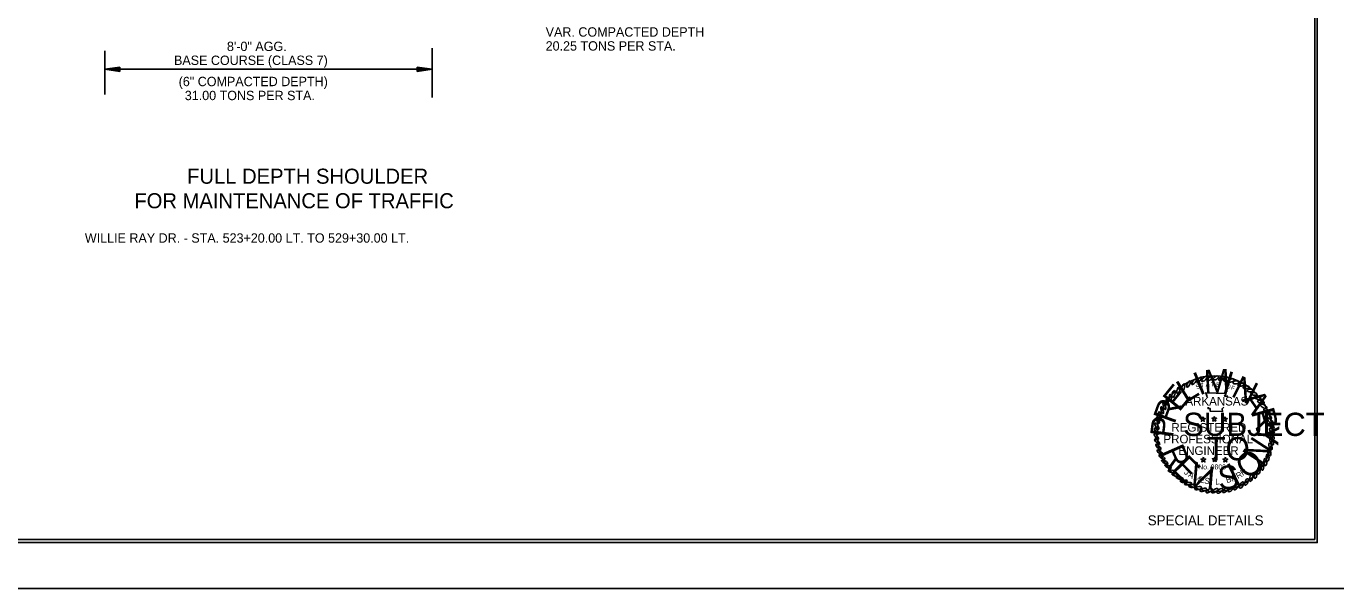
# Model space of a CAD drawing. Extents: x 714919 to 718439, y 1619644 to 1621844.
# Drawn here: x 716329 to 718439, y 1619644 to 1620545 of the extents above; entities that cross this region are included whole.
import ezdxf

# ---------------------------------------------------------------- set-up
doc = ezdxf.new("R2010")
doc.units = 0
for name, color, linetype in [('Default', 7, 'Continuous'), ('R_Border', 7, 'Continuous'), ('R_Border Notes', 7, 'Continuous'), ('R_Border PE', 7, 'Continuous'), ('R_Border Prem', 7, 'Continuous'), ('R_No Plot', 7, 'Continuous')]:
    doc.layers.add(name, color=color, linetype=linetype)

msp = doc.modelspace()

# ---------------------------------------------------------------- linework, layer by layer
at = {"layer": 'Default'}
for p, q in [((716454.5, 1620505.4), (716454.5, 1620435.4)), ((716979.2, 1620509.8), (716979.2, 1620431)), ((716478.7, 1620479.6), (716454.5, 1620475.9)), ((716478.7, 1620479), (716458.5, 1620475.9)), ((716478.7, 1620472.3), (716478.7, 1620479.6)), ((716955.1, 1620479.6), (716979.2, 1620475.9)), ((716955.1, 1620479.6), (716955.1, 1620472.3)), ((716955.1, 1620479), (716975.2, 1620475.9)), ((716454.5, 1620475.9), (716979.2, 1620475.9)), ((716478.7, 1620472.3), (716454.5, 1620475.9)), ((716478.7, 1620472.9), (716458.5, 1620475.9)), ((716478.7, 1620478.3), (716462.7, 1620475.9)), ((716478.7, 1620473.5), (716462.7, 1620475.9)), ((716478.7, 1620477.7), (716466.7, 1620475.9)), ((716478.7, 1620474.1), (716466.7, 1620475.9)), ((716478.7, 1620477.1), (716470.8, 1620475.9)), ((716478.7, 1620474.8), (716470.8, 1620475.9)), ((716478.7, 1620476.5), (716474.9, 1620475.9)), ((716478.7, 1620475.4), (716474.9, 1620475.9)), ((716955.1, 1620478.3), (716971, 1620475.9)), ((716955.1, 1620477.7), (716967, 1620475.9)), ((716955.1, 1620477.1), (716962.9, 1620475.9)), ((716955.1, 1620476.5), (716958.9, 1620475.9)), ((716955.1, 1620472.3), (716979.2, 1620475.9)), ((716955.1, 1620474.8), (716962.9, 1620475.9)), ((716955.1, 1620473.5), (716971, 1620475.9)), ((716955.1, 1620472.9), (716975.2, 1620475.9)), ((716955.1, 1620474.1), (716967, 1620475.9)), ((716955.1, 1620475.4), (716958.9, 1620475.9))]:
    msp.add_line(p, q, dxfattribs=at)
at = {"layer": 'R_Border'}
for p, q in [((718393.2, 1619722.5), (718393.1, 1621777.1)), ((718393.2, 1619722.5), (715231.2, 1619722.5)), ((714919.1, 1619643.5), (718439.3, 1619643.8))]:
    msp.add_line(p, q, dxfattribs=at)
at = {"layer": 'R_Border PE'}
for points in [[(718220.5, 1619951), (718218.4, 1619957.5), (718251, 1619956.6), (718248.6, 1619952.2), (718253.6, 1619951.9), (718253.3, 1619951.3)], [(718247.1, 1619934.7), (718244.4, 1619931.8), (718245, 1619927.3), (718225.5, 1619927.9), (718225.5, 1619932.1), (718222, 1619932.1), (718222, 1619934.7)]]:
    msp.add_lwpolyline(points, dxfattribs=at)
for points in [[(718213.7, 1619919), (718214.6, 1619916.1), (718217.5, 1619916.1), (718215.1, 1619914.6), (718216, 1619911.6), (718213.7, 1619913.4), (718211.3, 1619911.6), (718212.2, 1619914.6), (718209.8, 1619916.1), (718212.8, 1619916.1)], [(718232, 1619919.3), (718232.9, 1619916.7), (718235.6, 1619916.7), (718233.5, 1619914.9), (718234.4, 1619912.2), (718232, 1619913.7), (718229.6, 1619912.2), (718230.5, 1619914.9), (718228.2, 1619916.7), (718231.1, 1619916.7)], [(718248.9, 1619919), (718249.8, 1619916.1), (718252.7, 1619916.1), (718250.4, 1619914.6), (718251.3, 1619911.6), (718248.9, 1619913.4), (718246.5, 1619911.6), (718247.4, 1619914.6), (718245, 1619916.1), (718248, 1619916.1)], [(718214.6, 1619854.2), (718215.4, 1619851.2), (718218.4, 1619851.2), (718216, 1619849.8), (718216.9, 1619846.8), (718214.6, 1619848.6), (718212.2, 1619846.8), (718213.1, 1619849.8), (718210.7, 1619851.2), (718213.7, 1619851.2)], [(718232.9, 1619854.5), (718233.8, 1619851.8), (718236.5, 1619851.8), (718234.1, 1619850.1), (718235.3, 1619847.4), (718232.9, 1619848.9), (718230.5, 1619847.4), (718231.4, 1619850.1), (718229.1, 1619851.8), (718232, 1619851.8)], [(718249.8, 1619854.2), (718250.7, 1619851.2), (718253.6, 1619851.2), (718251.3, 1619849.8), (718252.1, 1619846.8), (718249.8, 1619848.6), (718247.4, 1619846.8), (718248.3, 1619849.8), (718245.9, 1619851.2), (718248.9, 1619851.2)]]:
    msp.add_lwpolyline(points, close=True, dxfattribs=at)
for centre, major_axis, ratio in [((718190.8, 1619971.3), (-2.46, -5.15), 0.329518), ((718199.8, 1619975.2), (-3.58, -4.44), 0.329518), ((718207.9, 1619978.2), (-3.64, -4.4), 0.329518), ((718216.6, 1619980), (-4.59, -4.21), 0.348728), ((718225, 1619980.5), (-3.87, -3.02), 0.44237), ((718234.7, 1619981.3), (-4.21, -2.45), 0.475469), ((718243.4, 1619980.4), (-4.21, -2.45), 0.475469), ((718251.5, 1619978.9), (-4.21, -2.45), 0.475469), ((718259.4, 1619977), (-4.64, -1.48), 0.475469), ((718266.9, 1619974.1), (-4.79, -0.89), 0.475469), ((718274.7, 1619970.6), (-4.85, -0.42), 0.475469), ((718161.4, 1619949.5), (0, -5.7), 0.322879), ((718166.6, 1619955.5), (-1.53, -5.49), 0.391724), ((718174.5, 1619961.8), (-1.53, -5.49), 0.394697), ((718182.4, 1619966.4), (-1.53, -5.49), 0.375751), ((718283.1, 1619966.3), (-4.85, -0.42), 0.475469), ((718289.7, 1619961.1), (-4.87, 0.11), 0.475469), ((718295.3, 1619955.8), (-5.09, 0.7), 0.451028), ((718301.6, 1619949.5), (-5.17, 1.18), 0.436264), ((718148.5, 1619929.5), (1.57, -5.48), 0.322879), ((718152.2, 1619936.2), (1.57, -5.48), 0.322879), ((718156.6, 1619943.4), (0, -5.7), 0.322879), ((718306.8, 1619943.1), (-5.3, 1.59), 0.418512), ((718311, 1619935.9), (-4.99, 2.77), 0.40589), ((718316.1, 1619928), (-4.66, 3.28), 0.40589), ((718140.2, 1619904.1), (3.04, -4.83), 0.322879), ((718141.8, 1619913.6), (1.57, -5.48), 0.322879), ((718144.9, 1619921.6), (1.57, -5.48), 0.322879), ((718319.2, 1619920), (-4.3, 3.75), 0.40589), ((718321.8, 1619912.2), (-4.3, 3.75), 0.40589), ((718323.5, 1619904.5), (-4.1, 3.96), 0.40589), ((718139.2, 1619887.6), (3.04, -4.83), 0.322879), ((718139.7, 1619896.1), (3.04, -4.83), 0.322879), ((718324.4, 1619896.2), (-3.5, 4.5), 0.40589), ((718324.5, 1619887.9), (-2.77, 4.99), 0.40589), ((718140.6, 1619879), (3.92, -4.14), 0.322879), ((718142.5, 1619870.6), (3.92, -4.14), 0.322879), ((718320.2, 1619862.1), (-1.02, 5.61), 0.40589), ((718322, 1619871.6), (-1.48, 5.51), 0.40589), ((718324, 1619879.4), (-2.3, 5.22), 0.40589), ((718145, 1619861.8), (4.29, -3.76), 0.322879), ((718148.3, 1619854.3), (4.67, -3.27), 0.322879), ((718152.6, 1619846.6), (5.13, -2.49), 0.322879), ((718313.7, 1619846.6), (-0.33, 5.69), 0.40589), ((718317.4, 1619853.4), (-0.33, 5.69), 0.40589), ((718157.9, 1619839.3), (5.13, -2.49), 0.322879), ((718163.9, 1619831.7), (5.58, -1.19), 0.322879), ((718169.6, 1619825.9), (5.58, -1.19), 0.322879), ((718291, 1619821), (1.36, 5.54), 0.40589), ((718298, 1619825.8), (0.91, 5.63), 0.40589), ((718303.5, 1619832.9), (0.91, 5.63), 0.40589), ((718309.1, 1619839), (0.27, 5.7), 0.40589), ((718176.6, 1619820.9), (5.58, -1.19), 0.322879), ((718183.4, 1619815.7), (5.68, 0.48), 0.322879), ((718190.1, 1619811.8), (5.68, 0.48), 0.322879), ((718197.2, 1619808), (5.68, 0.48), 0.40589), ((718206.2, 1619804.6), (5.5, 1.52), 0.40589), ((718214.5, 1619801.9), (5.5, 1.52), 0.40589), ((718223.8, 1619800.6), (4.91, 2.91), 0.40589), ((718233, 1619800.5), (4.91, 2.91), 0.40589), ((718241.1, 1619800.4), (4.63, 3.33), 0.40589), ((718250.1, 1619801.6), (4.36, 3.68), 0.40589), ((718258.6, 1619803), (4.08, 3.98), 0.40589), ((718267.3, 1619806.7), (3.39, 4.59), 0.40589), ((718275.7, 1619809.5), (2.43, 5.16), 0.40589), ((718283.7, 1619814.6), (2.26, 5.24), 0.40589)]:
    msp.add_ellipse(centre, major_axis=major_axis, ratio=ratio, dxfattribs=at)
at = {"layer": 'R_Border Prem'}
msp.add_circle((718232.7, 1619892.1), 92.6, dxfattribs=at)
at = {"layer": 'R_No Plot'}
msp.add_lwpolyline([(715227.2, 1619717.3), (718397.1, 1619717.4), (718397.2, 1621782.5), (715227.1, 1621782.3)], close=True, dxfattribs=at)

# ---------------------------------------------------------------- texts
at = {"layer": 'Default'}
for s, height, p in [('VAR. COMPACTED DEPTH ', 15, (717160.9, 1620528.3)), ('20.25 TONS PER STA.', 15, (717160.9, 1620505.9)), ('8\'-0" AGG.', 15, (716650.3, 1620505.2)), ('BASE COURSE (CLASS 7)', 15, (716565.5, 1620482.9)), ('(6" COMPACTED DEPTH)', 15, (716573, 1620448.9)), ('31.00 TONS PER STA.', 15, (716582.8, 1620426.5)), ('FULL DEPTH SHOULDER ', 24.168, (716586.5, 1620292.5)), ('FOR MAINTENANCE OF TRAFFIC ', 24.168, (716502, 1620253.2)), ('WILLIE RAY DR. - STA. 523+20.00 LT. TO 529+30.00 LT.', 15, (716422.7, 1620198.1))]:
    msp.add_text(s, height=height, dxfattribs=at).set_placement(p)
at = {"layer": 'R_Border Notes'}
msp.add_text('SPECIAL DETAILS', height=16, rotation=359.9984, dxfattribs=at).set_placement((718125.4, 1619745.1))
at = {"layer": 'R_Border PE'}
for s, height, rotation, p in [('T', 6.91, 14.9633, (718211, 1619965.2)), ('A', 6.91, 5.7234, (718218.4, 1619967)), ('T', 6.91, 1.1035, (718226.7, 1619967.6)), ('E', 6.91, 356.4836, (718234.7, 1619967.6)), ('ARKANSAS', 13.81, 0.0018, (718185.8, 1619937.1)), ('S', 6.91, 19.5832, (718203.6, 1619962.8)), ('O', 6.91, 342.6239, (718250.1, 1619965.5)), ('F', 6.91, 338.004, (718257.8, 1619963.1)), ('REGISTERED', 13.81, 0.0018, (718163.3, 1619895.1)), ('PROFESSIONAL', 13.814, 0.0018, (718150.6, 1619876.4)), ('ENGINEER', 13.81, 0.0018, (718174.6, 1619857.8)), ('J', 9.6, 322.4185, (718182.8, 1619828.4)), ('A', 9.6, 328.0189, (718189.3, 1619823.6)), ('M', 9.6, 333.6193, (718197.6, 1619818.8)), ('No. 9808', 7.89, 0.0018, (718206.4, 1619834.7)), ('A', 9.6, 24.0229, (718261.2, 1619815.2)), ('R', 9.6, 29.6233, (718270, 1619819.2)), ('R', 9.6, 35.2237, (718277.9, 1619824.1)), ('E', 9.6, 344.8201, (718207.1, 1619814.7)), ('S', 9.6, 350.4205, (718215.5, 1619812.3)), ('L', 9.6, 1.6213, (718233.8, 1619810.4)), ('.', 9.6, 7.2217, (718242.7, 1619811)), ('B', 9.6, 18.4225, (718252.4, 1619812.5))]:
    msp.add_text(s, height=height, rotation=rotation, dxfattribs=at).set_placement(p)
at = {"layer": 'R_Border Prem'}
for s, height, rotation, p in [('M', 37.2, 2.6961, (718216.3, 1619956.8)), ('E', 37.2, 50.9867, (718175.6, 1619925.5)), ('L', 37.2, 31.6705, (718186.6, 1619940.5)), ('I', 37.2, 22.0124, (718208.2, 1619952.7)), ('I', 37.2, 343.3799, (718242.6, 1619957.4)), ('N', 37.2, 333.7218, (718257.2, 1619952.9)), ('A', 37.2, 304.7474, (718274.7, 1619946.4)), ('R', 37.2, 70.3029, (718168.2, 1619905.9)), ('R', 37.2, 285.4312, (718290.8, 1619927.6)), ('P', 37.2, 82.6107, (718165.7, 1619884.2)), ('SUBJECT', 37.24, 0.0018, (718182.1, 1619888.3)), ('Y', 37.2, 266.1149, (718299.4, 1619907.6)), ('R', 37.2, 293.7657, (718146.4, 1619863.9)), ('TO', 37.24, 0.0018, (718219.7, 1619849.2)), ('N', 37.2, 57.1396, (718306.4, 1619839.7)), ('E', 37.2, 314.328, (718162.4, 1619834.7)), ('V', 37.2, 334.8903, (718185.5, 1619814.4)), ('O', 37.2, 36.5773, (718283.7, 1619817.5)), ('I', 37.2, 355.4526, (718218.3, 1619802.6)), ('S', 37.2, 5.7338, (718239.8, 1619802)), ('I', 37.2, 26.2961, (718264.8, 1619807.1))]:
    msp.add_text(s, height=height, rotation=rotation, dxfattribs=at).set_placement(p)

doc.saveas('drawing.dxf')
